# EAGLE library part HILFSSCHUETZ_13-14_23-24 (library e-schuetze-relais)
Hilfsschütz mit 2 Schließern
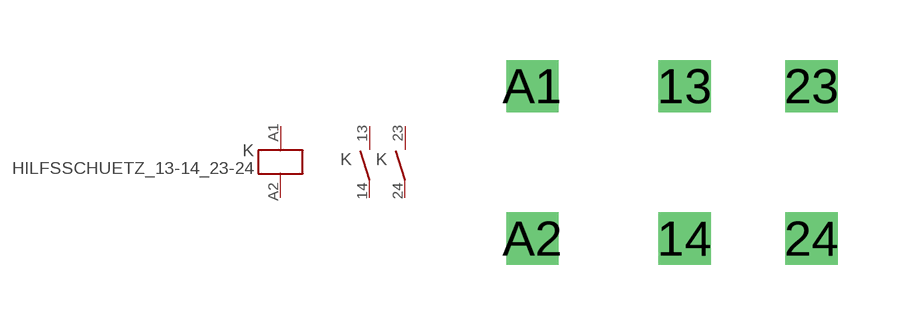
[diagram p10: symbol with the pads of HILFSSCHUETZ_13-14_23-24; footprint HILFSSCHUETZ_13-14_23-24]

Designator prefix K; gates _=SPULE 1=SCHLIESSER 2=SCHLIESSER

## HILFSSCHUETZ_13-14_23-24  [HILFSSCHUETZ_13-14_23-24]
13  1:3  pas
14  1:4  pas
23  2:3  pas
24  2:4  pas
A1  _:A1  in
A2  _:A2  in

## Footprint HILFSSCHUETZ_13-14_23-24 (pad centres in mm)
Dummy
drill 0.8 square: 13 0,1.905; 14 0,-1.905; 23 3.175,1.905; 24 3.175,-1.905; A1 -3.81,1.905; A2 -3.81,-1.905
